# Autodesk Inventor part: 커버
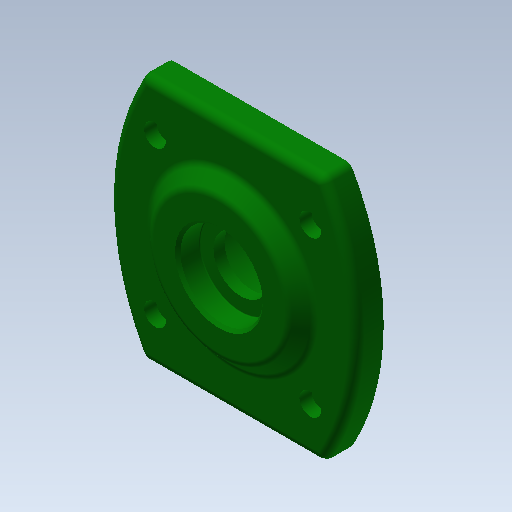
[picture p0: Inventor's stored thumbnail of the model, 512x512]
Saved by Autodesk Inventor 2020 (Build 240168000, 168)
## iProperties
Created: 2016-05
Part Number: 커버
Document SubType Name: Modeling
Designer: mduedu
Density: 2.71 g/cm^3
Material: 알루미늄 6061
Appearance: 진녹색
Author: mduedu
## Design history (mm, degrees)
sketch "스케치1"
  geometry: L1 (0, 0)-(-37.029, 37.029); L2 (0, 0)-(0, 45); L3 (0, 0)-(45, 0); L4 (32.942, 45)-(-32.942, 45); L5 (32.942, -45)-(-32.942, -45); C1 r 25 at (0, 0); A1 r 90 centre (45, 0) between (-32.942, 45) and (-32.942, -45); A2 r 90 centre (-45, 0) between (32.942, -45) and (32.942, 45); 1 further point
  constraints: 10 end point, 6 point on circle, 3 centre point, 2 horizontal alignment, 2 parallel, 1 coincident, 1 horizontal, 1 midpoint, 2 other
  dimensions: "d28" = 90 distance between centres of A2 A1; "d30" = 50 diameter of C1; "d31" = 45 deg angle of L2 L1; "d36" = 45 distance from line of L2 A1.centre (= 0.5 x d28); "d37" = 90 distance between parallel lines of L4 L5
extrude "돌출1" new body sketch "스케치1" distance "d0" = 10; taper "d1" = 0 deg
extrude "돌출2" join sketch "스케치1" distance "d2" = 12; taper "d3" = 0 deg
sketch "스케치2"
  geometry: C1 r 30 at (0, 0); 1 further point
  constraints: 1 centre point, 1 coincident
  dimensions: "d4" = 60 diameter of C1
extrude "돌출3" join sketch "스케치2" distance "d5" = 5; taper "d6" = -45 deg
sketch "스케치3"
  geometry: C1 r 1.621 at (-28.284, 28.284) reference; C2 r 1.621 at (28.284, 28.284) reference; C3 r 1.621 at (28.284, -28.284) reference; C4 r 1.621 at (-28.284, -28.284) reference; 1 further point
hole "구멍1" sketch "스케치3" at (28.284, 28.284), (-28.284, 28.284), (-28.284, -28.284), (28.284, -28.284) diameter "d7" = 4.5; stored, may be unused: countersink angle "d11" = 90 deg, drill point angle "d13" = 118 deg; dims "d8" = 6, "d9" = 8, "d10" = 4.4, "d12" = 8
fillet "모깎기1" dims "d14" = 3
sketch "스케치4"
  geometry: L1 (-23.757, 15)-(23.757, 15) reference; L2 (25, -12)-(-25, -12) reference; L3 (0, -12)-(0, 15); L4 (-20, -12)-(-20, 0); L5 (-20, 0)-(-15, 0); L6 (-15, 0)-(-15, 3); L7 (-15, 3)-(-10, 3); L8 (-10, 3)-(-10, 7); L9 (-10, 7)-(-15, 7); L10 (-15, 7)-(-15, 15); 1 further point
  constraints: 16 end point, 6 parallel, 2 midpoint, 2 point on line, 1 perpendicular
  dimensions: "d15" = 40 diameter of L4 L3; "d16" = 30 diameter of L10 L3; "d17" = 8 distance of L9.end L10.end; "d18" = 12 distance of L4.start L4.end; "d19" = 3 distance of L5.end L6.end; "d20" = 30 diameter of L6 L3; "d21" = 20 diameter of L8 L3
revolve "회전1" sketch "스케치4" stored, may be unused: angle "d22" = 90 deg
fillet "모깎기2" dims "d23" = 3
fillet "모깎기3" dims "d24" = 0.3
chamfer "모따기1" distance "d25" = 1; stored, may be unused: second distance "d26" = 2, angle "d27" = 45 deg
node "솔리드1"
node "참조2"
node "참조3"
node "참조4"
node "참조5"
